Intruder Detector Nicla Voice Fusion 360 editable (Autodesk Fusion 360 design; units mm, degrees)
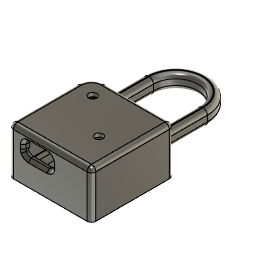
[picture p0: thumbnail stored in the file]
sketch "Sketch1" plane through (0, 0, 0) normal (0, 0, 1) x axis (1, 0, 0)
  line L1 (2.102, 22.86) -> (16.007, 22.86)
  line L2 (0, 19.553) -> (0, 20.758)
  line L3 (0, 17.013) -> (0, 18.547)
  line L4 (0, 14.473) -> (0, 16.007)
  line L5 (0, 11.933) -> (0, 13.467)
  line L6 (0, 9.393) -> (0, 10.927)
  line L7 (0, 6.853) -> (0, 8.387)
  line L8 (0, 4.313) -> (0, 5.847)
  line L9 (0, 1.773) -> (0, 3.307)
  line L10 (0, 0) -> (0, 0.767)
  line L11 (22.86, 0) -> (0, 0)
  line L12 (22.86, 0.767) -> (22.86, 0)
  line L13 (22.86, 3.307) -> (22.86, 1.773)
  line L14 (22.86, 5.847) -> (22.86, 4.313)
  line L15 (22.86, 8.387) -> (22.86, 6.853)
  line L16 (22.86, 10.927) -> (22.86, 9.393)
  line L17 (22.86, 13.467) -> (22.86, 11.933)
  line L18 (22.86, 16.007) -> (22.86, 14.473)
  line L19 (22.86, 18.547) -> (22.86, 17.013)
  line L20 (22.86, 21.087) -> (22.86, 19.553)
  line L21 (22.86, 22.86) -> (22.86, 22.093)
  line L22 (19.553, 22.86) -> (22.86, 22.86)
  line L23 (17.013, 22.86) -> (18.547, 22.86)
  line L24 (-0.5, 19.553) -> (-0.5, 20.7581)
  line L25 (19.553, 23.36) -> (23.36, 23.36)
  line L26 (19.553, 23.36) -> (16.007, 23.36)
  line L27 (2.1019, 23.36) -> (16.007, 23.36)
  line L28 (23.36, 23.36) -> (23.36, -0.5)
  line L29 (-0.5, -0.5) -> (-0.5, 19.553)
  line L30 (-0.5, -0.5) -> (23.36, -0.5)
  line L31 (-1.75, -1.75) -> (24.61, -1.75)
  line L32 (-1.75, -1.75) -> (-1.75, 19.553)
  line L33 (-1.75, 19.553) -> (-1.75, 20.7584)
  line L34 (2.1016, 24.61) -> (16.007, 24.61)
  line L35 (19.553, 24.61) -> (16.007, 24.61)
  line L36 (19.553, 24.61) -> (24.61, 24.61)
  line L37 (24.61, 24.61) -> (24.61, -1.75)
  line L38 (22.86, 21.087) -> (22.86, 22.093)
  line L39 (22.86, 1.773) -> (22.86, 0.767)
  line L40 (0, 1.773) -> (0, 0.767)
  line L41 (18.547, 22.86) -> (17.013, 22.86)
  line L42 (22.86, 22.86) -> (19.553, 22.86)
  line L43 (22.86, 22.093) -> (22.86, 22.86)
  line L44 (22.86, 19.553) -> (22.86, 21.087)
  line L45 (22.86, 17.013) -> (22.86, 18.547)
  line L46 (22.86, 14.473) -> (22.86, 16.007)
  line L47 (22.86, 11.933) -> (22.86, 13.467)
  line L48 (22.86, 9.393) -> (22.86, 10.927)
  line L49 (22.86, 6.853) -> (22.86, 8.387)
  line L50 (22.86, 4.313) -> (22.86, 5.847)
  line L51 (22.86, 1.773) -> (22.86, 3.307)
  line L52 (22.86, 0) -> (22.86, 0.767)
  line L53 (0, 0) -> (22.86, 0)
  line L54 (0, 0.767) -> (0, 0)
  line L55 (0, 3.307) -> (0, 1.773)
  line L56 (0, 5.847) -> (0, 4.313)
  line L57 (0, 8.387) -> (0, 6.853)
  line L58 (0, 10.927) -> (0, 9.393)
  line L59 (0, 13.467) -> (0, 11.933)
  line L60 (0, 16.007) -> (0, 14.473)
  line L61 (0, 18.547) -> (0, 17.013)
  line L62 (0, 20.758) -> (0, 19.553)
  line L63 (16.007, 22.86) -> (2.102, 22.86)
  line L64 (-39.6, 25) -> (-20, 25)
  line L65 (-39.6, 5.4) -> (-39.6, 25)
  line L66 (-20, 5.4) -> (-39.6, 5.4)
  line L67 (-20, 25) -> (-20, 5.4)
  arc A1 centre (16.51, 22.86) radius 0.503 clockwise from (17.013, 22.86) to (16.007, 22.86)
  arc A2 centre (2.1032, 20.7568) radius 2.1032 clockwise from (0, 20.758) to (2.102, 22.86)
  arc A3 centre (0, 19.05) radius 0.503 clockwise from (0, 19.553) to (0, 18.547)
  arc A4 centre (0, 16.51) radius 0.503 clockwise from (0, 17.013) to (0, 16.007)
  arc A5 centre (0, 13.97) radius 0.503 clockwise from (0, 14.473) to (0, 13.467)
  arc A6 centre (0, 11.43) radius 0.503 clockwise from (0, 11.933) to (0, 10.927)
  arc A7 centre (0, 8.89) radius 0.503 clockwise from (0, 9.393) to (0, 8.387)
  arc A8 centre (0, 6.35) radius 0.503 clockwise from (0, 6.853) to (0, 5.847)
  arc A9 centre (0, 3.81) radius 0.503 clockwise from (0, 4.313) to (0, 3.307)
  arc A10 centre (22.86, 3.81) radius 0.503 clockwise from (22.86, 3.307) to (22.86, 4.313)
  arc A11 centre (22.86, 6.35) radius 0.503 clockwise from (22.86, 5.847) to (22.86, 6.853)
  arc A12 centre (22.86, 8.89) radius 0.503 clockwise from (22.86, 8.387) to (22.86, 9.393)
  arc A13 centre (22.86, 11.43) radius 0.503 clockwise from (22.86, 10.927) to (22.86, 11.933)
  arc A14 centre (22.86, 13.97) radius 0.503 clockwise from (22.86, 13.467) to (22.86, 14.473)
  arc A15 centre (22.86, 16.51) radius 0.503 clockwise from (22.86, 16.007) to (22.86, 17.013)
  arc A16 centre (22.86, 19.05) radius 0.503 clockwise from (22.86, 18.547) to (22.86, 19.553)
  arc A17 centre (19.05, 22.86) radius 0.503 clockwise from (19.553, 22.86) to (18.547, 22.86)
  arc A18 centre (22.86, 1.27) radius 0.003 clockwise from (22.86, 1.267) to (22.86, 1.273)
  arc A19 centre (0, 1.27) radius 0.003 clockwise from (0, 1.273) to (0, 1.267)
  arc A20 centre (0, 3.81) radius 0.003 clockwise from (0, 3.813) to (0, 3.807)
  arc A21 centre (0, 6.35) radius 0.003 clockwise from (0, 6.353) to (0, 6.347)
  arc A22 centre (0, 8.89) radius 0.003 clockwise from (0, 8.893) to (0, 8.887)
  arc A23 centre (0, 11.43) radius 0.003 clockwise from (0, 11.433) to (0, 11.427)
  arc A24 centre (0, 13.97) radius 0.003 clockwise from (0, 13.973) to (0, 13.967)
  arc A25 centre (0, 16.51) radius 0.003 clockwise from (0, 16.513) to (0, 16.507)
  arc A26 centre (0, 19.05) radius 0.003 clockwise from (0, 19.053) to (0, 19.047)
  arc A27 centre (2.1032, 20.7568) radius 2.6032 clockwise from (-0.5, 20.7581) to (2.1019, 23.36)
  arc A28 centre (16.51, 22.86) radius 0.003 clockwise from (16.513, 22.86) to (16.507, 22.86)
  arc A29 centre (19.05, 22.86) radius 0.003 clockwise from (19.053, 22.86) to (19.047, 22.86)
  arc A30 centre (22.86, 21.59) radius 0.003 clockwise from (22.86, 21.587) to (22.86, 21.593)
  arc A31 centre (22.86, 19.05) radius 0.003 clockwise from (22.86, 19.047) to (22.86, 19.053)
  arc A32 centre (22.86, 16.51) radius 0.003 clockwise from (22.86, 16.507) to (22.86, 16.513)
  arc A33 centre (22.86, 13.97) radius 0.003 clockwise from (22.86, 13.967) to (22.86, 13.973)
  arc A34 centre (22.86, 11.43) radius 0.003 clockwise from (22.86, 11.427) to (22.86, 11.433)
  arc A35 centre (22.86, 8.89) radius 0.003 clockwise from (22.86, 8.887) to (22.86, 8.893)
  arc A36 centre (22.86, 6.35) radius 0.003 clockwise from (22.86, 6.347) to (22.86, 6.353)
  arc A37 centre (22.86, 3.81) radius 0.003 clockwise from (22.86, 3.807) to (22.86, 3.813)
  arc A38 centre (2.1032, 20.7568) radius 3.8532 clockwise from (-1.75, 20.7584) to (2.1016, 24.61)
  circle C1 centre (24.61, -1.75) radius 3.5
  circle C2 centre (24.61, 24.61) radius 3.5
  circle C3 centre (-1.75, -1.75) radius 3.5
  circle C4 centre (-1.75, 24.61) radius 4
  circle C5 centre (17.029, 8.408) radius 0.4
  arc A39 centre (19.05, 22.86) radius 0.503 clockwise from (19.553, 22.86) to (18.547, 22.86)
  arc A40 centre (22.86, 21.59) radius 0.503 clockwise from (22.86, 21.087) to (22.86, 22.093)
  arc A41 centre (22.86, 19.05) radius 0.503 clockwise from (22.86, 18.547) to (22.86, 19.553)
  arc A42 centre (22.86, 16.51) radius 0.503 clockwise from (22.86, 16.007) to (22.86, 17.013)
  arc A43 centre (22.86, 13.97) radius 0.503 clockwise from (22.86, 13.467) to (22.86, 14.473)
  arc A44 centre (22.86, 11.43) radius 0.503 clockwise from (22.86, 10.927) to (22.86, 11.933)
  arc A45 centre (22.86, 8.89) radius 0.503 clockwise from (22.86, 8.387) to (22.86, 9.393)
  arc A46 centre (22.86, 6.35) radius 0.503 clockwise from (22.86, 5.847) to (22.86, 6.853)
  arc A47 centre (22.86, 3.81) radius 0.503 clockwise from (22.86, 3.307) to (22.86, 4.313)
  arc A48 centre (22.86, 1.27) radius 0.503 clockwise from (22.86, 0.767) to (22.86, 1.773)
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  point P128 (24.61, -1.75)
  point P137 (24.61, -1.75)
  point P136 (24.61, 24.61)
  point P138 (24.61, 24.61)
  point P129 (-1.75, -1.75)
  point P139 (-1.75, -1.75)
  point P57 (22.86, 22.093)
  point P141 (22.86, 22.093)
  point P56 (22.86, 21.087)
  point P142 (22.86, 21.087)
  point P33 (22.86, 0.767)
  point P143 (22.86, 0.767)
  point P34 (22.86, 1.773)
  point P144 (22.86, 1.773)
  point P30 (0, 0.767)
  point P145 (0, 0.767)
  point P29 (0, 1.773)
  point P146 (0, 1.773)
  point P231 (-20, 25)
  point P232 (-39.6, 25)
  point P234 (-20, 5.4)
  concentric A3 A26
  concentric A16 A31
  concentric A15 A32
  concentric A14 A33
  concentric A13 A34
  concentric A12 A35
  concentric A11 A36
  concentric A10 A37
  parallel L25 L26
  vertical L28
  vertical L29
  perpendicular L29 L30
  coincident P128 P137
  coincident P136 P138
  coincident P129 P139
  coincident P57 P141
  coincident P56 P142
  coincident P33 P143
  coincident P34 P144
  coincident P30 P145
  coincident P29 P146
  horizontal L64
  vertical L65
  horizontal L66
  vertical L67
  dimension "d4" = -1.25
  dimension "d5" diameter C1 = 7
  dimension "d6" diameter C2 = 7
  dimension "d7" diameter C3 = 7
  dimension "d8" diameter C4 = 8
  dimension "d73" distance P231 P232 = 19.6
  dimension "d74" distance P231 P234 = 19.6
extrude "Extrude1" new body sketch "Sketch1" profile of A1 L1 A2 L2 A3 L3 A4 L4 A5 L5 A6 L6 A7 L7 A8 L8 A9 L9 L10 L11 L12 L13 A10 L14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 along normal blind 1.25
extrude "Extrude2" add sketch "Sketch1" profile of L24 A27 L25 L26 L27 L28 L29 L30 L31 L33 L32 A38 L34 L37 L35 L36 C1 C2 C3 C4 along normal blind 1.25
extrude "Extrude3" add sketch "Sketch1" profile of L24 A27 L25 L26 L27 L28 L29 L30 L31 L33 L32 A38 L34 L37 L35 L36 C1 C2 C3 C4 against normal blind 11
extrude "Extrude4" add sketch "Sketch1" profile of A2 L10 L11 L12 L21 L22 A27 L25 L28 L29 L30 C1 C2 C3 C4 against normal blind 2
extrude "Extrude5" cut sketch "Sketch1" profile of A2 L10 L11 L12 L21 L22 A18 A19 A30 C1 C2 C3 C4 L38 L39 L40 against normal blind 1.8 and against normal blind 2.5
extrude "Extrude6" add of existing geometry blind 1.6
extrude "Extrude7" add of existing geometry blind 0.2
offset_faces "OffsetFaces1" distance -0.1
extrude "Extrude8" cut of existing geometry blind -0.1
extrude "Extrude9" cut of existing geometry blind -0.1
extrude "Extrude10" cut of existing geometry blind -0.1
extrude "Extrude11" cut of existing geometry blind -0.1
extrude "Extrude12" cut of existing geometry blind -0.1
extrude "Extrude13" cut of existing geometry blind -1.6
extrude "Extrude14" cut of existing geometry blind -0.1
extrude "Extrude15" cut of existing geometry blind -0.1
extrude "Extrude16" cut of existing geometry blind -0.15
extrude "Extrude17" cut of existing geometry blind -0.2
extrude "Extrude18" cut of existing geometry blind -1.6
offset_faces "OffsetFaces2" distance -0.1
extrude "Extrude19" cut of existing geometry blind -0.1
extrude "Extrude20" cut of existing geometry blind -0.15
extrude "Extrude21" cut of existing geometry blind -1.6
extrude "Extrude22" cut of existing geometry blind 5
extrude "Extrude23" cut of existing geometry blind -2
step "ReplaceFace1"
step "ReplaceFace2"
step "ReplaceFace3"
extrude "Extrude24" add of existing geometry blind 0.05
offset_faces "OffsetFaces3" distance -1.5
extrude "Extrude25" cut sketch "Sketch1" along normal blind 5
offset_faces "OffsetFaces4" distance -1
extrude "Extrude26" cut of existing geometry blind -1.6
delete_face "DeleteFace1"
delete_face "DeleteFace2"
offset_faces "OffsetFaces5" distance 2.5
sketch "Sketch2" plane through (0, 0, -11) normal (0, 0, -1) x axis (1, 0, 0)
  line L1 (2.1019, -23.36) -> (23.36, -23.36)
  line L2 (-0.5, 0.5) -> (-0.5, -20.7581)
  line L3 (23.36, 0.5) -> (-0.5, 0.5)
  line L4 (23.36, -23.36) -> (23.36, 0.5)
  line L5 (27.11, -27.11) -> (2.1016, -27.11)
  line L6 (27.11, 4.25) -> (27.11, -27.11)
  line L7 (-4.25, 4.25) -> (27.11, 4.25)
  line L8 (-4.25, -20.7584) -> (-4.25, 4.25)
  line L9 (2.1014, -25.36) -> (25.36, -25.36)
  line L10 (-2.5, 2.5) -> (-2.5, -20.7586)
  line L11 (25.36, 2.5) -> (-2.5, 2.5)
  line L12 (25.36, -25.36) -> (25.36, 2.5)
  arc A1 centre (2.1032, -20.7568) radius 2.6032 clockwise from (2.1019, -23.36) to (-0.5, -20.7581)
  arc A2 centre (2.1032, -20.7568) radius 6.3532 clockwise from (2.1016, -27.11) to (-4.25, -20.7584)
  arc A3 centre (2.1032, -20.7568) radius 4.6032 clockwise from (2.1014, -25.36) to (-2.5, -20.7586)
  dimension "d66" = -2
extrude "Extrude27" cut sketch "Sketch2" profile of L1 A1 L2 L3 L4 L11 A3 L9 L10 L12 against normal blind 6
extrude "Extrude28" add of existing geometry blind 2
extrude "Extrude29" add of existing geometry blind 2
sketch "Sketch4" plane through (-2.5, 0, 0) normal (1, 0, 0) x axis (0, 1, 0)
  line L1 (20.7586, -5) -> (20.7586, -15)
  line L2 (-2.5, -5) -> (20.7586, -5)
  line L3 (-2.5, -15) -> (-2.5, -5)
  line L4 (20.7586, -15) -> (-2.5, -15)
  line L5 (-2.5, -10) -> (20.7586, -10)
  line L6 (-2.5, -12.5) -> (-2.5, -10)
  line L7 (20.7586, -12.5) -> (-2.5, -12.5)
  line L8 (20.7586, -10) -> (20.7586, -12.5)
  point P6 (20.7586, -10)
  point P9 (20.7586, -12.5)
  horizontal L5
  vertical L6
  horizontal L7
  vertical L8
  midpoint L1 P6
  dimension "d79" distance P6 P9 = 2.5
extrude "Extrude31" new body sketch "Sketch4" profile of L1 L3 L5 L6 L7 L8 along normal blind 1.5 bodies "tri1"
chamfer "Chamfer1" distance 1.2
copy_paste_bodies "CopyPasteBodies2"
move "Move2" RotateAngle -180
move "Move3"
move "Move4"
move "Move5"
sketch "Sketch5" plane through (25.36, 0, 0) normal (-1, 0, 0) x axis (0, -1, 0)
  line L1 (2.5, -5) -> (2.5, -15)
  line L2 (-25.36, -5) -> (2.5, -5)
  line L3 (-25.36, -15) -> (-25.36, -5)
  line L4 (2.5, -15) -> (-25.36, -15)
  line L5 (-20.7586, -12.5) -> (-20.7586, -10)
move "Move6"
sketch "Sketch6" plane through (0, 0, -15) normal (0, 0, -1) x axis (1, 0, 0)
  line L1 (2.1014, -25.36) -> (25.36, -25.36)
  line L2 (-2.5, 2.5) -> (-2.5, -20.7586)
  line L3 (25.36, 2.5) -> (-2.5, 2.5)
  line L4 (25.36, -25.36) -> (25.36, 2.5)
  line L5 (27.11, -27.11) -> (2.1016, -27.11)
  line L6 (27.11, 4.25) -> (27.11, -27.11)
  line L7 (-4.25, 4.25) -> (27.11, 4.25)
  line L8 (-4.25, -20.7584) -> (-4.25, 4.25)
  line L9 (2.1019, -22.36) -> (22.36, -22.36)
  line L10 (0.5, -0.5) -> (0.5, -20.7581)
  line L11 (22.36, -0.5) -> (0.5, -0.5)
  line L12 (22.36, -22.36) -> (22.36, -0.5)
  arc A1 centre (2.1032, -20.7568) radius 4.6032 clockwise from (2.1014, -25.36) to (-2.5, -20.7586)
  arc A2 centre (2.1032, -20.7568) radius 6.3532 clockwise from (2.1016, -27.11) to (-4.25, -20.7584)
  arc A3 centre (2.1032, -20.7568) radius 1.6032 clockwise from (2.1019, -22.36) to (0.5, -20.7581)
  dimension "d84" = 3
extrude "Extrude32" new body sketch "Sketch6" profile of L1 A1 L2 L3 L4 L11 L9 A3 L12 L10 against normal blind 4.5
move "Move7"
extrude "Extrude33" cut of existing geometry blind 35
step "ReplaceFace4"
step "ReplaceFace5"
delete_face "DeleteFace3"
delete_face "DeleteFace4"
delete_face "DeleteFace5"
delete_face "DeleteFace6"
delete_face "DeleteFace7"
delete_face "DeleteFace8"
sketch "Sketch7" plane through (22.36, 0, 0) normal (-1, 0, 0) x axis (0, -1, 0)
  line L1 (-0.5, -15) -> (-22.36, -15)
  line L2 (-0.5, -10.5) -> (-0.5, -15)
  line L3 (-22.36, -10.5) -> (-0.5, -10.5)
  line L4 (-22.36, -15) -> (-22.36, -10.5)
  line L5 (-22.36, -15) -> (-0.5, -15)
  line L6 (-22.36, -13.75) -> (-22.36, -15)
  line L7 (-0.5, -13.75) -> (-22.36, -13.75)
  line L8 (-0.5, -15) -> (-0.5, -13.75)
  point P3 (-0.5, -15)
  point P6 (-0.5, -15)
  point P9 (-0.5, -13.75)
  horizontal L5
  vertical L6
  horizontal L7
  vertical L8
  coincident P3 P6
  dimension "d89" distance P6 P9 = 1.25
extrude "Extrude34" add sketch "Sketch7" profile of L1 L2 L4 L5 L6 L7 L8 along normal blind 22
extrude "Extrude35" cut of existing geometry blind -0.8
extrude "Extrude36" cut of existing geometry blind -0.9
sketch "Sketch8" plane through (25.36, 0, 0) normal (1, 0, 0) x axis (0, 1, 0)
  line L1 (20.7586, -11.2) -> (-2.5, -11.2)
  line L2 (20.7586, -14.3) -> (20.7586, -11.2)
  line L3 (-2.5, -14.3) -> (20.7586, -14.3)
  line L4 (-2.5, -15) -> (-2.5, -14.3)
  line L5 (25.36, -15) -> (-2.5, -15)
  line L6 (25.36, -10.5) -> (25.36, -15)
  line L7 (-2.5, -10.5) -> (25.36, -10.5)
  line L8 (-2.5, -11.2) -> (-2.5, -10.5)
  line L9 (20.7586, -10.5) -> (20.7586, -11.2)
  point P3 (20.7586, -11.2)
  point P10 (20.7586, -11.2)
  point P11 (20.7586, -10.5)
  coincident P3 P10
  coincident L7 P11
  perpendicular L7 L9
extrude "Extrude37" cut sketch "Sketch8" profile of L1 L7 L8 L9 against normal blind 0.8
extrude "Extrude38" cut of existing geometry blind -1.2
offset_faces "OffsetFaces6" distance -0.5
offset_faces "OffsetFaces7" distance -0.5
offset_faces "OffsetFaces8" distance -0.3
move "Move9"
move "Move10"
extrude "Extrude39" cut of existing geometry blind -0.5
extrude "Extrude40" cut of existing geometry blind -0.5
extrude "Extrude41" cut of existing geometry blind -0.5
extrude "Extrude42" cut of existing geometry blind -0.5
offset_faces "OffsetFaces10" distance -0.5
delete_face "DeleteFace9"
extrude "Extrude43" cut of existing geometry blind -0.5
delete_face "DeleteFace10"
offset_faces "OffsetFaces11" distance -0.5
sketch "Sketch9" plane through (0, 0, -15) normal (0, 0, -1) x axis (1, 0, 0)
  line L1 (25.06, -25.06) -> (2.1014, -25.06)
  line L2 (25.06, 2.2) -> (25.06, -25.06)
  line L3 (-2.2, 2.2) -> (25.06, 2.2)
  line L4 (-2.2, -20.7586) -> (-2.2, 2.2)
  line L5 (10.5807, -25.06) -> (13.5807, -25.06)
  line L6 (10.5807, -23.56) -> (10.5807, -25.06)
  line L7 (13.5807, -23.56) -> (10.5807, -23.56)
  line L8 (13.5807, -25.06) -> (13.5807, -23.56)
  arc A1 centre (2.1032, -20.7568) radius 4.3032 clockwise from (2.1014, -25.06) to (-2.2, -20.7586)
  point P8 (13.5807, -25.06)
  point P9 (10.5807, -25.06)
  point P11 (13.5807, -23.56)
  horizontal L5
  vertical L6
  horizontal L7
  vertical L8
  midpoint L1 P8
  dimension "d116" distance P8 P9 = 3
  dimension "d117" distance P8 P11 = 1.5
extrude "Extrude44" cut sketch "Sketch9" profile of L1 L5 L6 L7 L8 against normal blind 4.5
extrude "Extrude45" cut of existing geometry blind -0.5
offset_faces "OffsetFaces12" distance 1.5
offset_faces "OffsetFaces13" distance -1.5
chamfer "Chamfer2" distance 1
delete_face "DeleteFace11"
delete_face "DeleteFace12"
delete_face "DeleteFace13"
delete_face "DeleteFace14"
delete_face "DeleteFace15"
delete_face "DeleteFace16"
extrude "Extrude46" add of existing geometry blind 23.5
delete_face "DeleteFace17"
delete_face "DeleteFace18"
extrude "Extrude47" cut of existing geometry blind -2.6
delete_face "DeleteFace19"
extrude "Extrude48" add of existing geometry blind 23.5
extrude "Extrude49" cut of existing geometry blind -1.18
delete_face "DeleteFace20"
offset_faces "OffsetFaces14" distance -1.5
offset_faces "OffsetFaces15" distance 0.55 (= "1.25 mm - 0.7 mm")
move "Move11"
move "Move12"
extrude "Extrude50" cut of existing geometry blind 32
extrude "Extrude51" cut of existing geometry blind -6
offset_faces "OffsetFaces16" distance -0.3
offset_faces "OffsetFaces17" distance -0.3
offset_faces "OffsetFaces18" distance -0.5
offset_faces "OffsetFaces19" distance -0.5
offset_faces "OffsetFaces20" distance 1
offset_faces "OffsetFaces21" distance 1
offset_faces "OffsetFaces22" distance -2
combine "Combine2" bodies "tri1"
offset_faces "OffsetFaces23" distance -0.1
offset_faces "OffsetFaces24" distance -0.1
extrude "Extrude52" cut of existing geometry blind 8
offset_faces "OffsetFaces25" distance -0.65
step "TorusPrimitive" MinorDiameter 5 MajorDiameter 20
delete_face "DeleteFace21"
sketch "Sketch11" plane through (0, 0, 1.25) normal (0, 0, 1) x axis (-1, 0, 0)
  line L1 (-2.1016, -25.61) -> (-25.61, -25.61)
  line L2 (2.75, 2.75) -> (2.75, -20.7584)
  line L3 (-25.61, 2.75) -> (2.75, 2.75)
  line L4 (-25.61, -25.61) -> (-25.61, 2.75)
  line L5 (-19.6773, -25.61) -> (-19.6773, -39.9035)
  line L6 (-4.3431, -25.61) -> (-4.3431, -39.9035)
  line L7 (-22.9346, -25.61) -> (-22.9346, -39.9035)
  line L8 (-1.0858, -25.61) -> (-1.0858, -39.9035)
  line L9 (-1.0858, -25.5) -> (-1.0858, -25.61)
  circle C1 centre (-3.85, -19.4623) radius 1.4
  arc A1 centre (-2.1032, -20.7568) radius 4.8532 clockwise from (2.75, -20.7584) to (-2.1016, -25.61)
  circle C2 centre (-17.029, -8.408) radius 1.4
  arc A2 centre (-12.0102, -39.9035) radius 7.6671 clockwise from (-4.3431, -39.9035) to (-19.6773, -39.9035)
  arc A3 centre (-12.0102, -39.9035) radius 10.9244 clockwise from (-1.0858, -39.9035) to (-22.9346, -39.9035)
  point P12 (-19.6773, -25.61)
  point P14 (-4.3431, -25.61)
  coincident L1 P12
  tangent L5 A2
  vertical L5
  coincident L1 P14
  tangent L6 A2
  parallel L5 L6
  dimension "d153" = 3.2573
extrude "Extrude53" new body sketch "Sketch11" profile of L1 A1 A2 L5 L6 L7 A3 L8 L9 along normal blind 5 bodies "hook"
fillet "Fillet2" radius 1.5
fillet "Fillet3" radius 1.5
fillet "Fillet4" radius 1.5
fillet "Fillet5" radius 1.5
move "Move14"
fillet "Fillet6" radius 1.5
fillet "Fillet7" radius 1.5
combine "Combine3" bodies "hook"
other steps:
base_feature "Base Feature" bodies "Box"
named bodies: "BoxG", "tri1", "Box", "Cap", "hook"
